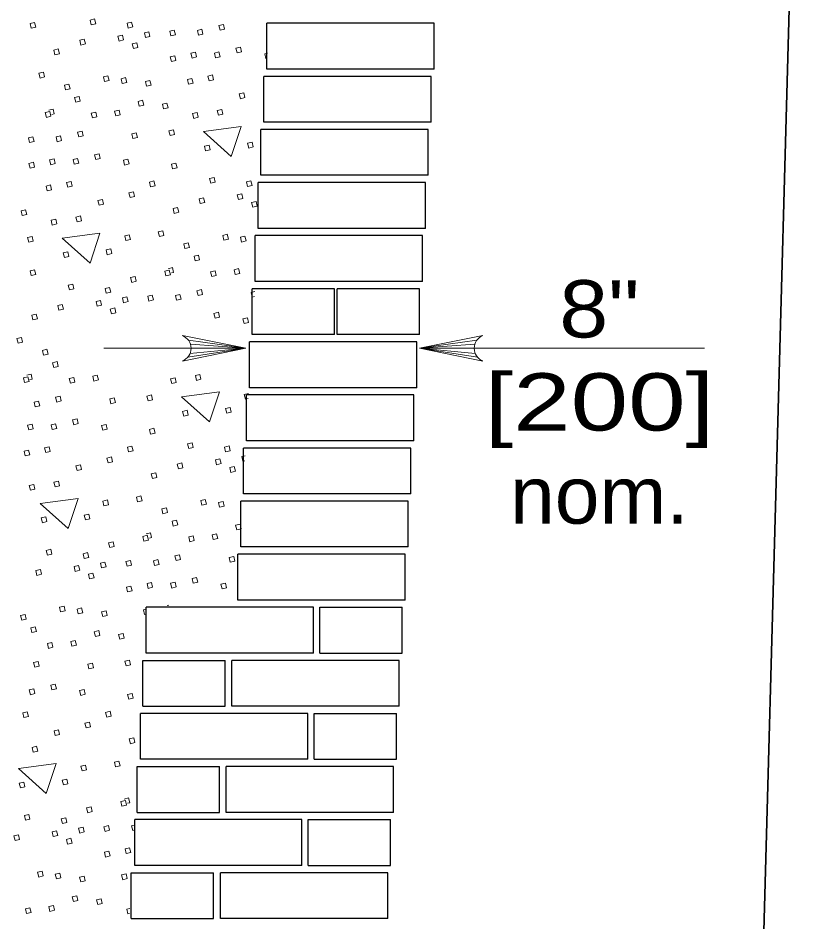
# Model space of a CAD drawing. Extents: x 750.7 to 784.7, y 860.1 to 882.1.
# Drawn here: x 761.807 to 763.987, y 870.002 to 872.527 of the extents above; entities that cross this region are included whole.
import ezdxf
from ezdxf.enums import TextEntityAlignment as Align

# ---------------------------------------------------------------- set-up
doc = ezdxf.new("R2010")
doc.units = 0
doc.header["$LTSCALE"] = 0.064
doc.layers.add('1', color=7, linetype='Continuous', lineweight=13)

msp = doc.modelspace()

# ---------------------------------------------------------------- linework, layer by layer
at = {"layer": '1', "lineweight": 35}
msp.add_line((763.83808, 868.0415), (763.98708, 873.45325), dxfattribs=at)
at = {"layer": '1'}
for p, q in [((761.893, 872.26958), (761.90517, 872.27242)), ((762.22675, 871.82667), (762.23892, 871.82958)), ((762.28358, 871.62667), (762.44392, 871.60425)), ((763.08942, 871.62667), (762.92917, 871.60425)), ((762.04725, 871.60425), (762.44392, 871.60425)), ((762.28167, 871.5795), (762.44392, 871.60425)), ((762.28783, 871.58983), (762.44392, 871.60425)), ((762.289, 871.61558), (762.44392, 871.60425)), ((762.29067, 871.60425), (762.44392, 871.60425)), ((763.084, 871.61558), (762.92917, 871.60425)), ((763.08233, 871.60425), (762.92917, 871.60425)), ((763.08517, 871.58983), (762.92917, 871.60425)), ((763.09133, 871.5795), (762.92917, 871.60425)), ((762.93267, 871.60425), (763.72575, 871.60425)), ((761.83167, 871.529), (761.84383, 871.53183)), ((762.16542, 871.08608), (762.17758, 871.089)), ((762.22375, 870.88567), (762.228, 870.88667)), ((762.228, 870.88667), (762.22817, 870.886)), ((762.10408, 870.3455), (762.11625, 870.34842))]:
    msp.add_line(p, q, dxfattribs=at)
at = {"layer": '1', "lineweight": 25}
for p, q in [((762.462, 871.64258), (762.462, 871.77067)), ((762.6995, 871.64258), (762.6995, 871.77067)), ((762.69208, 871.64258), (762.462, 871.64258)), ((762.92967, 871.64258), (762.6995, 871.64258)), ((762.881, 870.753), (762.881, 870.88108)), ((762.38633, 870.60475), (762.38633, 870.73283)), ((762.65092, 870.753), (762.881, 870.753)), ((762.15625, 870.60475), (762.38633, 870.60475)), ((762.86483, 870.4565), (762.86483, 870.5845)), ((762.63467, 870.4565), (762.86483, 870.4565)), ((762.37017, 870.30825), (762.37017, 870.43625)), ((762.14, 870.30825), (762.37017, 870.30825)), ((762.84858, 870.15992), (762.84858, 870.288)), ((762.6185, 870.15992), (762.84858, 870.15992)), ((762.35392, 870.01167), (762.35392, 870.13975)), ((762.12383, 870.01167), (762.35392, 870.01167))]:
    msp.add_line(p, q, dxfattribs=at)
at = {"layer": '1'}
for points in [[(761.85333, 872.5145), (761.85658, 872.50125), (761.844, 872.49825), (761.84083, 872.5115)], [(762.02142, 872.52417), (762.02467, 872.511), (762.01208, 872.508), (762.00892, 872.52125)], [(762.1245, 872.51492), (762.12767, 872.50175), (762.11517, 872.49875), (762.11192, 872.512)], [(762.38117, 872.50875), (762.38433, 872.4955), (762.37175, 872.4925), (762.36858, 872.50575)], [(762.099, 872.47883), (762.10225, 872.46558), (762.08967, 872.46258), (762.0865, 872.47583)], [(762.17292, 872.48842), (762.17608, 872.47517), (762.1635, 872.47217), (762.16033, 872.48542)], [(762.24383, 872.49308), (762.24708, 872.47983), (762.2345, 872.47683), (762.23133, 872.49008)], [(762.321, 872.49533), (762.32417, 872.48208), (762.31167, 872.47908), (762.30842, 872.49233)], [(761.99225, 872.46758), (761.99542, 872.45433), (761.98292, 872.45133), (761.97967, 872.46458)], [(762.13908, 872.45758), (762.14225, 872.44433), (762.12967, 872.44133), (762.1265, 872.45458)], [(761.91967, 872.44042), (761.92283, 872.42717), (761.91025, 872.42417), (761.90708, 872.43742)], [(762.30292, 872.43117), (762.30617, 872.41792), (762.29358, 872.41492), (762.29042, 872.42817)], [(762.36867, 872.43208), (762.37192, 872.41883), (762.35933, 872.41583), (762.35617, 872.42908)], [(762.42883, 872.44542), (762.432, 872.43217), (762.4195, 872.42925), (762.41625, 872.4425)], [(762.24542, 872.4215), (762.24858, 872.40825), (762.23608, 872.40525), (762.23283, 872.4185)], [(761.87817, 872.37542), (761.88133, 872.36217), (761.86875, 872.35917), (761.86558, 872.37242)], [(762.05833, 872.36567), (762.06158, 872.35242), (762.049, 872.34942), (762.04583, 872.36267)], [(762.10775, 872.36033), (762.11092, 872.34708), (762.09833, 872.34408), (762.09517, 872.35733)], [(762.17583, 872.35225), (762.179, 872.339), (762.1665, 872.336), (762.16325, 872.34925)], [(762.29308, 872.35817), (762.29633, 872.345), (762.28375, 872.342), (762.28058, 872.35525)], [(762.35067, 872.36783), (762.35383, 872.35458), (762.34125, 872.35158), (762.33808, 872.36483)], [(761.94942, 872.34208), (761.95258, 872.32883), (761.94, 872.32583), (761.93683, 872.33908)], [(761.97792, 872.30775), (761.98108, 872.2945), (761.9685, 872.2915), (761.96533, 872.30475)], [(762.43808, 872.31767), (762.44133, 872.30442), (762.42875, 872.30142), (762.42558, 872.31467)], [(762.15542, 872.297), (762.15858, 872.28375), (762.146, 872.28075), (762.14283, 872.294)], [(762.2235, 872.289), (762.22675, 872.27575), (762.21417, 872.27275), (762.211, 872.286)], [(761.896, 872.26558), (761.89925, 872.25233), (761.88667, 872.24933), (761.8835, 872.26258)], [(762.02433, 872.26375), (762.02758, 872.25058), (762.015, 872.24758), (762.01183, 872.26075)], [(762.08992, 872.26975), (762.09308, 872.2565), (762.0805, 872.2535), (762.07733, 872.26675)], [(762.3075, 872.26267), (762.31075, 872.24942), (762.29817, 872.24642), (762.295, 872.25967)], [(762.37667, 872.27167), (762.37992, 872.25842), (762.36733, 872.25542), (762.36417, 872.26867)], [(762.43133, 872.2235), (762.32592, 872.2095), (762.40342, 872.13983)], [(761.92592, 872.19767), (761.92917, 872.18442), (761.91658, 872.18142), (761.91342, 872.19467)], [(761.98608, 872.211), (761.98925, 872.19783), (761.97675, 872.19483), (761.9735, 872.20808)], [(762.13758, 872.2065), (762.14075, 872.19325), (762.12817, 872.19025), (762.125, 872.2035)], [(762.24142, 872.21458), (762.24458, 872.20133), (762.232, 872.19833), (762.22883, 872.21158)], [(761.84883, 872.19533), (761.852, 872.18208), (761.83942, 872.17908), (761.83625, 872.19233)], [(762.34108, 872.17175), (762.34425, 872.1585), (762.33167, 872.15558), (762.3285, 872.16875)], [(762.46125, 872.17983), (762.46442, 872.16658), (762.45192, 872.16358), (762.44867, 872.17683)], [(762.03375, 872.14775), (762.03692, 872.1345), (762.02442, 872.1315), (762.02117, 872.14475)], [(761.85033, 872.12383), (761.85358, 872.11058), (761.841, 872.10758), (761.83783, 872.12083)], [(761.90792, 872.13342), (761.91108, 872.12017), (761.8985, 872.11717), (761.89533, 872.13042)], [(761.97367, 872.13433), (761.97683, 872.12108), (761.96425, 872.11817), (761.96108, 872.13133)], [(762.1145, 872.13233), (762.11775, 872.11908), (762.10517, 872.11608), (762.102, 872.12933)], [(762.24858, 872.12158), (762.25175, 872.10833), (762.23917, 872.10533), (762.236, 872.11858)], [(762.18708, 872.07167), (762.19033, 872.05842), (762.17775, 872.05542), (762.17458, 872.06867)], [(762.35517, 872.08133), (762.35842, 872.06808), (762.34583, 872.06508), (762.34258, 872.07833)], [(762.45825, 872.07208), (762.46142, 872.05883), (762.44892, 872.05583), (762.44567, 872.06908)], [(761.89808, 872.0605), (761.90125, 872.04725), (761.88867, 872.04425), (761.8855, 872.0575)], [(761.95558, 872.07017), (761.95875, 872.05692), (761.94625, 872.05392), (761.943, 872.06717)], [(762.12958, 872.04133), (762.13283, 872.02808), (762.12025, 872.02508), (762.11708, 872.03833)], [(762.326, 872.02467), (762.32917, 872.01142), (762.31658, 872.00842), (762.31342, 872.02167)], [(762.43275, 872.036), (762.43592, 872.02275), (762.42342, 872.01975), (762.42017, 872.033)], [(762.04308, 872.01992), (762.04625, 872.00667), (762.03367, 872.00375), (762.0305, 872.01692)], [(762.25342, 871.9975), (762.25658, 871.98425), (762.244, 871.98125), (762.24083, 871.9945)], [(762.47275, 872.01467), (762.476, 872.00142), (762.46342, 871.99842), (762.46025, 872.01167)], [(761.8285, 871.99125), (761.83167, 871.978), (761.81908, 871.975), (761.81592, 871.98825)], [(761.98158, 871.974), (761.98483, 871.96075), (761.97225, 871.95775), (761.96908, 871.971)], [(761.9125, 871.96492), (761.91567, 871.95167), (761.90308, 871.94867), (761.89992, 871.96192)], [(762.03625, 871.92583), (761.93083, 871.91183), (762.00842, 871.84208)], [(762.11825, 871.92133), (762.12142, 871.90808), (762.10883, 871.90508), (762.10567, 871.91833)], [(762.21192, 871.93258), (762.21508, 871.91933), (762.2025, 871.91633), (762.19933, 871.92958)], [(762.39208, 871.92283), (762.39533, 871.90958), (762.38275, 871.90658), (762.37958, 871.91983)], [(761.84633, 871.91692), (761.8495, 871.90367), (761.837, 871.90067), (761.83375, 871.91392)], [(762.28317, 871.89917), (762.28633, 871.886), (762.27375, 871.883), (762.27058, 871.89625)], [(762.44142, 871.91742), (762.44467, 871.90417), (762.43208, 871.90117), (762.42892, 871.91442)], [(761.946, 871.87408), (761.94917, 871.86083), (761.93667, 871.85783), (761.93342, 871.87108)], [(762.06617, 871.88208), (762.06933, 871.86883), (762.05683, 871.86583), (762.05358, 871.87908)], [(762.31158, 871.86483), (762.31483, 871.85158), (762.30225, 871.84858), (762.29908, 871.86183)], [(761.8535, 871.82392), (761.85667, 871.81067), (761.84417, 871.80767), (761.84092, 871.82092)], [(762.22975, 871.82267), (762.233, 871.80942), (762.22042, 871.80642), (762.21725, 871.81967)], [(762.35808, 871.82092), (762.36133, 871.80767), (762.34875, 871.80467), (762.34558, 871.81792)], [(762.42358, 871.82683), (762.42683, 871.81358), (762.41425, 871.81058), (762.41108, 871.82383)], [(762.13425, 871.80475), (762.1375, 871.7915), (762.12492, 871.7885), (762.12167, 871.80175)], [(761.96008, 871.78358), (761.96333, 871.77033), (761.95075, 871.76742), (761.94758, 871.78058)], [(762.06317, 871.77433), (762.06642, 871.76108), (762.05383, 871.75817), (762.05058, 871.77133)], [(762.31983, 871.76817), (762.323, 871.75492), (762.31042, 871.75192), (762.30725, 871.76517)], [(762.11158, 871.74783), (762.11475, 871.73458), (762.10217, 871.73158), (762.099, 871.74483)], [(762.18258, 871.7525), (762.18575, 871.73925), (762.17317, 871.73625), (762.17, 871.7495)], [(762.25967, 871.75475), (762.26292, 871.7415), (762.25033, 871.7385), (762.24717, 871.75175)], [(761.93092, 871.727), (761.93408, 871.71375), (761.92158, 871.71075), (761.91833, 871.724)], [(762.03767, 871.73825), (762.04092, 871.725), (762.02833, 871.722), (762.02517, 871.73525)], [(761.85833, 871.69983), (761.8615, 871.68658), (761.849, 871.68358), (761.84575, 871.69683)], [(762.07775, 871.717), (762.08092, 871.70375), (762.06833, 871.70075), (762.06517, 871.714)], [(762.3675, 871.70483), (762.37067, 871.69158), (762.35817, 871.68858), (762.35492, 871.70183)], [(762.44825, 871.6895), (762.4515, 871.67625), (762.43892, 871.67325), (762.43575, 871.6865)], [(761.81683, 871.63483), (761.82, 871.62158), (761.8075, 871.61858), (761.80425, 871.63183)], [(761.88808, 871.6015), (761.89125, 871.58825), (761.87867, 871.58525), (761.8755, 871.5985)], [(761.91658, 871.56717), (761.91975, 871.55392), (761.90717, 871.55092), (761.904, 871.56417)], [(761.83475, 871.525), (761.83792, 871.51175), (761.82533, 871.50875), (761.82217, 871.522)], [(761.963, 871.52317), (761.96625, 871.50992), (761.95367, 871.507), (761.9505, 871.52017)], [(762.02858, 871.52917), (762.03175, 871.51592), (762.01917, 871.51292), (762.016, 871.52617)], [(762.24617, 871.52208), (762.24942, 871.50883), (762.23683, 871.50583), (762.23367, 871.51908)], [(762.31533, 871.53108), (762.31858, 871.51783), (762.306, 871.51483), (762.30283, 871.52808)], [(761.92475, 871.47042), (761.92792, 871.45717), (761.91542, 871.45417), (761.91217, 871.46742)], [(762.07625, 871.46583), (762.07942, 871.45267), (762.06692, 871.44967), (762.06367, 871.46292)], [(762.18008, 871.474), (762.18325, 871.46075), (762.17075, 871.45775), (762.1675, 871.471)], [(762.37, 871.48292), (762.26458, 871.46892), (762.34208, 871.39925)], [(761.86458, 871.45708), (761.86783, 871.44383), (761.85525, 871.44083), (761.85208, 871.45408)], [(762.27975, 871.43117), (762.28292, 871.41792), (762.27033, 871.41492), (762.26717, 871.42817)], [(762.39992, 871.43925), (762.40308, 871.426), (762.39058, 871.423), (762.38733, 871.43625)], [(761.84658, 871.39283), (761.84975, 871.37958), (761.83717, 871.37658), (761.834, 871.38983)], [(761.91233, 871.39375), (761.9155, 871.3805), (761.90292, 871.3775), (761.89975, 871.39075)], [(761.97242, 871.40717), (761.97567, 871.39392), (761.96308, 871.39092), (761.95992, 871.40417)], [(762.05325, 871.39175), (762.05642, 871.3785), (762.04383, 871.3755), (762.04067, 871.38875)], [(762.18725, 871.381), (762.19042, 871.36775), (762.17792, 871.36475), (762.17467, 871.378)], [(762.29383, 871.34075), (762.29708, 871.3275), (762.2845, 871.3245), (762.28133, 871.33775)], [(761.83675, 871.31992), (761.83992, 871.30667), (761.82733, 871.30367), (761.82417, 871.31692)], [(761.89425, 871.32958), (761.89742, 871.31633), (761.88492, 871.31333), (761.88167, 871.32658)], [(762.12575, 871.331), (762.129, 871.31783), (762.11642, 871.31483), (762.11325, 871.32808)], [(762.39692, 871.3315), (762.40008, 871.31825), (762.38758, 871.31525), (762.38433, 871.3285)], [(762.06825, 871.30075), (762.0715, 871.2875), (762.05892, 871.2845), (762.05575, 871.29775)], [(762.37142, 871.29533), (762.37467, 871.28217), (762.36208, 871.27917), (762.35892, 871.29242)], [(761.98175, 871.27933), (761.98492, 871.26608), (761.97242, 871.26308), (761.96917, 871.27633)], [(762.26467, 871.28408), (762.26783, 871.27083), (762.25533, 871.26783), (762.25208, 871.28108)], [(762.4115, 871.27408), (762.41467, 871.26083), (762.40208, 871.25783), (762.39892, 871.27108)], [(762.19208, 871.25692), (762.19525, 871.24367), (762.18267, 871.24067), (762.1795, 871.25392)], [(761.85117, 871.22433), (761.85433, 871.21108), (761.84175, 871.20808), (761.83858, 871.22133)], [(761.92033, 871.23333), (761.9235, 871.22017), (761.91092, 871.21717), (761.90775, 871.23042)], [(762.15058, 871.19192), (762.15375, 871.17875), (762.14117, 871.17575), (762.138, 871.189)], [(761.97492, 871.18525), (761.8695, 871.17117), (761.94708, 871.1015)], [(762.05692, 871.18075), (762.06008, 871.1675), (762.0475, 871.1645), (762.04433, 871.17775)], [(762.33075, 871.18217), (762.334, 871.169), (762.32142, 871.166), (762.31825, 871.17925)], [(762.38017, 871.17683), (762.38333, 871.16358), (762.37075, 871.16058), (762.36758, 871.17383)], [(762.00483, 871.1415), (762.00808, 871.12825), (761.9955, 871.12525), (761.99233, 871.1385)], [(762.22183, 871.15858), (762.225, 871.14542), (762.21242, 871.14242), (762.20925, 871.15558)], [(761.88467, 871.1335), (761.88783, 871.12025), (761.87533, 871.11725), (761.87208, 871.1305)], [(762.25033, 871.12425), (762.2535, 871.111), (762.24092, 871.108), (762.23775, 871.12125)], [(762.42783, 871.1135), (762.431, 871.10025), (762.41842, 871.09725), (762.41525, 871.1105)], [(762.36225, 871.08625), (762.3655, 871.073), (762.35292, 871.07), (762.34975, 871.08325)], [(762.07292, 871.06417), (762.07617, 871.05092), (762.06358, 871.04792), (762.06042, 871.06117)], [(762.16842, 871.08208), (762.17167, 871.06883), (762.15908, 871.06583), (762.15592, 871.07908)], [(762.29675, 871.08033), (762.3, 871.06708), (762.28742, 871.06408), (762.28425, 871.07733)], [(761.89883, 871.043), (761.902, 871.02975), (761.88942, 871.02675), (761.88625, 871.04)], [(762.00183, 871.03375), (762.00508, 871.0205), (761.9925, 871.0175), (761.98933, 871.03075)], [(762.12125, 871.01183), (762.12442, 870.99867), (762.11183, 870.99567), (762.10867, 871.00892)], [(762.19833, 871.01417), (762.20158, 871.00092), (762.189, 870.99792), (762.18583, 871.01117)], [(762.2585, 871.02758), (762.26167, 871.01433), (762.24908, 871.01133), (762.24592, 871.02458)], [(762.41, 871.023), (762.41317, 871.00975), (762.40058, 871.00675), (762.39742, 871.02)], [(761.86958, 870.98642), (761.87275, 870.97317), (761.86025, 870.97017), (761.857, 870.98342)], [(761.97633, 870.99767), (761.97958, 870.98442), (761.967, 870.98142), (761.96383, 870.99467)], [(762.05025, 871.00725), (762.05342, 870.994), (762.04092, 870.991), (762.03767, 871.00425)], [(762.01642, 870.97642), (762.01958, 870.96317), (762.007, 870.96017), (762.00383, 870.97342)], [(762.30617, 870.96425), (762.30933, 870.951), (762.29683, 870.948), (762.29358, 870.96125)], [(762.12275, 870.94033), (762.126, 870.92708), (762.11342, 870.92408), (762.11025, 870.93733)], [(762.18033, 870.95), (762.1835, 870.93675), (762.17092, 870.93375), (762.16775, 870.947)], [(762.24608, 870.95092), (762.24925, 870.93767), (762.23667, 870.93467), (762.2335, 870.94792)], [(762.38692, 870.94883), (762.39017, 870.93567), (762.37758, 870.93267), (762.37442, 870.94592)], [(761.93575, 870.8845), (761.93892, 870.87125), (761.92633, 870.86825), (761.92317, 870.8815)], [(761.82675, 870.86092), (761.82992, 870.84767), (761.81742, 870.84467), (761.81417, 870.85792)], [(761.98508, 870.87908), (761.98825, 870.86583), (761.97567, 870.86292), (761.9725, 870.87608)], [(762.05317, 870.87108), (762.05642, 870.85783), (762.04383, 870.85483), (762.04067, 870.86808)], [(761.85525, 870.82658), (761.85842, 870.81333), (761.84583, 870.81033), (761.84267, 870.82358)], [(762.03275, 870.81583), (762.03592, 870.80258), (762.02342, 870.79958), (762.02017, 870.81283)], [(761.96725, 870.78858), (761.97042, 870.77533), (761.95783, 870.77233), (761.95467, 870.78558)], [(762.10092, 870.80783), (762.10408, 870.79458), (762.0915, 870.79158), (762.08833, 870.80483)], [(761.90175, 870.78258), (761.90492, 870.76933), (761.89233, 870.76633), (761.88917, 870.77958)], [(762.11875, 870.73342), (762.12192, 870.72017), (762.10942, 870.71717), (762.10617, 870.73042)], [(761.86342, 870.72983), (761.86658, 870.71658), (761.85408, 870.71358), (761.85083, 870.72683)], [(762.01492, 870.72525), (762.01808, 870.712), (762.00558, 870.70908), (762.00233, 870.72225)], [(761.91108, 870.66658), (761.91433, 870.65333), (761.90175, 870.65033), (761.89858, 870.66358)], [(761.851, 870.65317), (761.85417, 870.63992), (761.84167, 870.63692), (761.83842, 870.65017)], [(761.99192, 870.65117), (761.99508, 870.63792), (761.9825, 870.63492), (761.97933, 870.64817)], [(762.12592, 870.64042), (762.12908, 870.62717), (762.11658, 870.62417), (762.11333, 870.63742)], [(761.83292, 870.589), (761.83608, 870.57575), (761.82358, 870.57275), (761.82033, 870.586)], [(762.0645, 870.59042), (762.06767, 870.57717), (762.05508, 870.57425), (762.05192, 870.58742)], [(762.00692, 870.56017), (762.01017, 870.54692), (761.99758, 870.54392), (761.99442, 870.55717)], [(761.92042, 870.53875), (761.92358, 870.5255), (761.91108, 870.5225), (761.90783, 870.53575)], [(762.13075, 870.51633), (762.13392, 870.50308), (762.12142, 870.50008), (762.11817, 870.51333)], [(761.859, 870.49275), (761.86217, 870.47958), (761.84958, 870.47658), (761.84642, 870.48975)], [(761.91358, 870.44467), (761.80817, 870.43058), (761.88575, 870.36092)], [(761.99558, 870.44017), (761.99875, 870.42692), (761.98617, 870.42392), (761.983, 870.43717)], [(762.08925, 870.45133), (762.09242, 870.43808), (762.07992, 870.43517), (762.07667, 870.44833)], [(761.82333, 870.39292), (761.82658, 870.37967), (761.814, 870.37667), (761.81075, 870.38992)], [(761.9435, 870.40092), (761.94675, 870.38767), (761.93417, 870.38467), (761.931, 870.39792)], [(762.10717, 870.3415), (762.11033, 870.32825), (762.09775, 870.32525), (762.09458, 870.3385)], [(762.01158, 870.32358), (762.01483, 870.31033), (762.00225, 870.30733), (761.99908, 870.32058)], [(761.8375, 870.30242), (761.84067, 870.28917), (761.82808, 870.28617), (761.82492, 870.29942)], [(761.9405, 870.29317), (761.94375, 870.27992), (761.93117, 870.27692), (761.928, 870.29017)], [(761.91508, 870.25708), (761.91825, 870.24383), (761.90567, 870.24083), (761.9025, 870.25408)], [(761.98892, 870.26667), (761.99208, 870.25342), (761.97958, 870.25042), (761.97633, 870.26367)], [(762.05992, 870.27125), (762.06308, 870.25808), (762.0505, 870.25508), (762.04733, 870.26825)], [(761.80825, 870.24583), (761.8115, 870.23258), (761.79892, 870.22958), (761.79575, 870.24283)], [(761.95508, 870.23583), (761.95825, 870.22258), (761.94575, 870.21958), (761.9425, 870.23283)], [(762.119, 870.20933), (762.12217, 870.19617), (762.10958, 870.19317), (762.10642, 870.20642)], [(762.06142, 870.19975), (762.06467, 870.1865), (762.05208, 870.1835), (762.04892, 870.19675)], [(761.87442, 870.14392), (761.87758, 870.13067), (761.865, 870.12767), (761.86183, 870.14092)], [(761.92375, 870.1385), (761.92692, 870.12525), (761.91442, 870.12225), (761.91117, 870.1355)], [(761.99183, 870.1305), (761.99508, 870.11725), (761.9825, 870.11425), (761.97933, 870.1275)], [(762.10917, 870.13642), (762.11233, 870.12317), (762.09975, 870.12017), (762.09658, 870.13342)], [(761.97142, 870.07525), (761.97467, 870.062), (761.96208, 870.059), (761.95892, 870.07225)], [(762.03958, 870.06717), (762.04275, 870.054), (762.03017, 870.051), (762.027, 870.06425)], [(761.84042, 870.042), (761.84358, 870.02875), (761.831, 870.02575), (761.82783, 870.039)], [(761.90592, 870.048), (761.90908, 870.03475), (761.89658, 870.03175), (761.89333, 870.045)]]:
    msp.add_lwpolyline(points, close=True, dxfattribs=at)
at = {"layer": '1', "lineweight": 25}
for points in [[(762.97017, 872.38392), (762.97017, 872.512), (762.5025, 872.512)], [(762.97017, 872.38392), (762.5025, 872.38392), (762.5025, 872.512)], [(762.96208, 872.23567), (762.96208, 872.36375), (762.49442, 872.36375)], [(762.96208, 872.23567), (762.49442, 872.23567), (762.49442, 872.36375)], [(762.954, 872.08742), (762.954, 872.2155), (762.48625, 872.2155)], [(762.954, 872.08742), (762.48625, 872.08742), (762.48625, 872.2155)], [(762.94583, 871.93917), (762.94583, 872.06717), (762.47817, 872.06717)], [(762.94583, 871.93917), (762.47817, 871.93917), (762.47817, 872.06717)], [(762.93775, 871.79092), (762.93775, 871.91892), (762.47008, 871.91892)], [(762.93775, 871.79092), (762.47008, 871.79092), (762.47008, 871.91892)], [(762.69208, 871.64258), (762.69208, 871.77067), (762.462, 871.77067)], [(762.92967, 871.64258), (762.92967, 871.77067), (762.6995, 871.77067)], [(762.92158, 871.49433), (762.92158, 871.62242), (762.45383, 871.62242)], [(762.92158, 871.49433), (762.45383, 871.49433), (762.45383, 871.62242)], [(762.91342, 871.34608), (762.91342, 871.47417), (762.44575, 871.47417)], [(762.91342, 871.34608), (762.44575, 871.34608), (762.44575, 871.47417)], [(762.90533, 871.19783), (762.90533, 871.32583), (762.43767, 871.32583)], [(762.90533, 871.19783), (762.43767, 871.19783), (762.43767, 871.32583)], [(762.89725, 871.04958), (762.89725, 871.17758), (762.42958, 871.17758)], [(762.89725, 871.04958), (762.42958, 871.04958), (762.42958, 871.17758)], [(762.88917, 870.90125), (762.88917, 871.02933), (762.42142, 871.02933)], [(762.88917, 870.90125), (762.42142, 870.90125), (762.42142, 871.02933)], [(762.63333, 870.753), (762.63333, 870.88108), (762.16567, 870.88108)], [(762.63333, 870.753), (762.16567, 870.753), (762.16567, 870.88108)], [(762.65092, 870.753), (762.65092, 870.88108), (762.881, 870.88108)], [(762.15625, 870.60475), (762.15625, 870.73283), (762.38633, 870.73283)], [(762.87292, 870.60475), (762.87292, 870.73283), (762.40525, 870.73283)], [(762.87292, 870.60475), (762.40525, 870.60475), (762.40525, 870.73283)], [(762.61717, 870.4565), (762.61717, 870.58458), (762.14942, 870.5845)], [(762.61717, 870.4565), (762.14942, 870.4565), (762.14942, 870.5845)], [(762.63467, 870.4565), (762.63467, 870.5845), (762.86483, 870.5845)], [(762.14, 870.30825), (762.14, 870.43625), (762.37017, 870.43625)], [(762.85675, 870.30825), (762.85675, 870.43625), (762.389, 870.43625)], [(762.85675, 870.30825), (762.389, 870.30825), (762.389, 870.43625)], [(762.60092, 870.15992), (762.60092, 870.288), (762.13325, 870.288)], [(762.60092, 870.15992), (762.13325, 870.15992), (762.13325, 870.288)], [(762.6185, 870.15992), (762.6185, 870.288), (762.84858, 870.288)], [(762.12383, 870.01167), (762.12383, 870.13975), (762.35392, 870.13975)], [(762.8405, 870.01167), (762.8405, 870.13975), (762.37283, 870.13975)], [(762.8405, 870.01167), (762.37283, 870.01167), (762.37283, 870.13975)]]:
    msp.add_lwpolyline(points, dxfattribs=at)
at = {"layer": '1'}
for points in [[(762.5035, 872.41458), (762.50025, 872.41383), (762.49708, 872.42708), (762.50433, 872.42875)], [(761.90517, 872.27242), (761.90833, 872.25925), (761.902, 872.25767)], [(762.23892, 871.82958), (762.24208, 871.81633), (762.23575, 871.81475)], [(762.468, 871.74875), (762.46192, 871.74733), (762.45875, 871.76058), (762.46875, 871.763)], [(762.26683, 871.56883), (762.44392, 871.60425), (762.26683, 871.63967)], [(763.10617, 871.56883), (762.92917, 871.60425), (763.10617, 871.63967)], [(761.84383, 871.53183), (761.847, 871.51858), (761.84067, 871.51708)], [(762.45025, 871.464), (762.44258, 871.46217), (762.43942, 871.47542), (762.451, 871.47817)], [(762.44133, 871.29), (762.43592, 871.28867), (762.43275, 871.30192), (762.44208, 871.30417)], [(762.17758, 871.089), (762.18075, 871.07575), (762.17442, 871.07417)], [(762.16458, 870.86158), (762.16108, 870.86075), (762.15792, 870.874), (762.16533, 870.87583)], [(762.11625, 870.34842), (762.11942, 870.33517), (762.11308, 870.33358)], [(762.13133, 870.25825), (762.12767, 870.25733), (762.1245, 870.27058), (762.13217, 870.27242)], [(762.1185, 870.02567), (762.11417, 870.02467), (762.111, 870.03792), (762.11933, 870.03983)]]:
    msp.add_lwpolyline(points, dxfattribs=at)
for centre, start, end in [((762.25252, 871.60432), 292.08605, 67.91218), ((763.12051, 871.60432), 112.08782, 247.91395)]:
    msp.add_arc(centre, 0.03822, start, end, dxfattribs=at)

# ---------------------------------------------------------------- texts
for s, width, p in [('8"', 1.15, (763.43212, 871.63458)), ('[200]', 1.35, (763.43221, 871.37458)), ('nom.', 1.05, (763.43217, 871.11458))]:
    msp.add_text(s, height=0.16, dxfattribs=dict(at, width=width)).set_placement(p, align=Align.CENTER)

doc.saveas('drawing.dxf')
